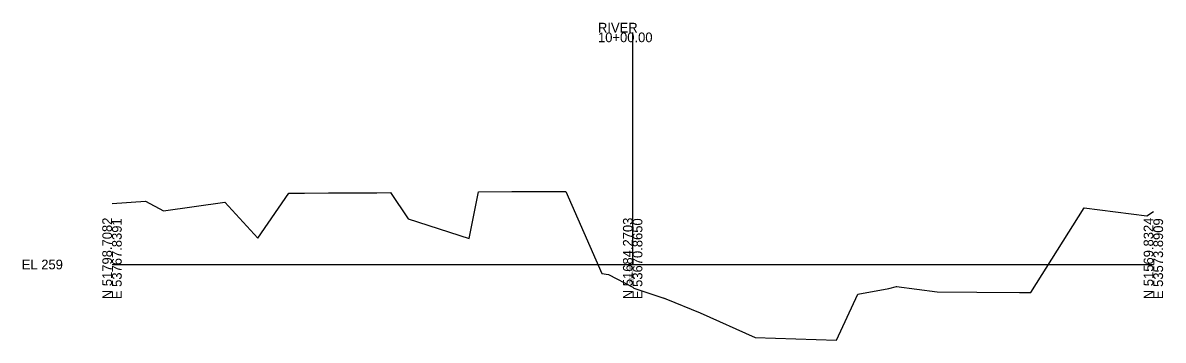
# Model space of a CAD drawing. Extents: x 5628 to 5956, y 92469 to 104012.
# Drawn here: x 5627.6 to 5956.2, y 99456.8 to 99548.3 of the extents above; entities that cross this region are included whole.
import ezdxf

# ---------------------------------------------------------------- set-up
doc = ezdxf.new("R2010")
doc.units = 0
for name, color, linetype in [('Level 10', 7, 'Continuous'), ('Level 60', 7, 'Continuous'), ('Level 63', 7, 'Continuous')]:
    doc.layers.add(name, color=color, linetype=linetype)

msp = doc.modelspace()

# ---------------------------------------------------------------- linework, layer by layer
at = {"layer": 'Level 60'}
for p, q in [((5653.34, 99496.2), (5662.95, 99496.85)), ((5662.95, 99496.85), (5668.21, 99494.08)), ((5695.34, 99486.23), (5704.26, 99499.13)), ((5704.26, 99499.13), (5708.37, 99499.19)), ((5708.37, 99499.19), (5708.82, 99499.22)), ((5708.82, 99499.22), (5715.69, 99499.24)), ((5715.69, 99499.24), (5716.11, 99499.31)), ((5716.11, 99499.31), (5729.59, 99499.31)), ((5729.59, 99499.31), (5733.53, 99499.33)), ((5733.53, 99499.33), (5738.66, 99491.73)), ((5756.28, 99486.06), (5758.91, 99499.51)), ((5758.91, 99499.51), (5768.57, 99499.63)), ((5768.57, 99499.63), (5784.07, 99499.68)), ((5784.07, 99499.68), (5794.5, 99476.02)), ((5668.21, 99494.08), (5685.89, 99496.55)), ((5685.89, 99496.55), (5695.34, 99486.23)), ((5918.09, 99470.55), (5933.39, 99494.99)), ((5933.39, 99494.99), (5951.46, 99492.65)), ((5951.46, 99492.65), (5953.34, 99493.88)), ((5738.66, 99491.73), (5756.28, 99486.06)), ((5794.5, 99476.02), (5796.39, 99475.73)), ((5796.39, 99475.73), (5803.4, 99472.06)), ((5803.4, 99472.06), (5803.71, 99471.74)), ((5803.71, 99471.74), (5812.87, 99468.74)), ((5868.25, 99470.04), (5877.13, 99471.72)), ((5877.13, 99471.72), (5879.36, 99472.29)), ((5879.36, 99472.29), (5879.45, 99472.15)), ((5879.36, 99472.29), (5891.05, 99470.76)), ((5891.05, 99470.76), (5902.48, 99470.64)), ((5902.48, 99470.64), (5914.82, 99470.51)), ((5914.82, 99470.51), (5918.09, 99470.55)), ((5812.25, 99468.98), (5812.87, 99468.74)), ((5812.87, 99468.74), (5822.74, 99464.62)), ((5862.03, 99456.76), (5868.25, 99470.04)), ((5822.74, 99464.62), (5838.65, 99457.5)), ((5838.65, 99457.5), (5862.03, 99456.76))]:
    msp.add_line(p, q, dxfattribs=at)
at = {"layer": 'Level 63'}
for p, q in [((5803.34, 99478.6), (5803.34, 99545.51)), ((5653.34, 99478.6), (5803.34, 99478.6)), ((5803.34, 99478.6), (5953.34, 99478.6))]:
    msp.add_line(p, q, dxfattribs=at)

# ---------------------------------------------------------------- texts
at = {"layer": 'Level 10'}
msp.add_text('255.75', height=1.2, rotation=90, dxfattribs=at).set_placement((5803.54, 99473.09))
at = {"layer": 'Level 63'}
for s, p in [('RIVER', (5793.34, 99545.51)), ('10+00.00', (5793.34, 99542.71)), ('EL 259', (5627.33, 99477.2))]:
    msp.add_text(s, height=2.8, dxfattribs=at).set_placement(p)
for s, p in [('N 51798.7082', (5653.34, 99468.6)), ('E 53767.8391', (5656.14, 99468.6)), ('N 51684.2703', (5803.34, 99468.59)), ('E 53670.8650', (5806.14, 99468.6)), ('N 51569.8324', (5953.34, 99468.6)), ('E 53573.8909', (5956.14, 99468.6))]:
    msp.add_text(s, height=2.8, rotation=90, dxfattribs=at).set_placement(p)

doc.saveas('drawing.dxf')
